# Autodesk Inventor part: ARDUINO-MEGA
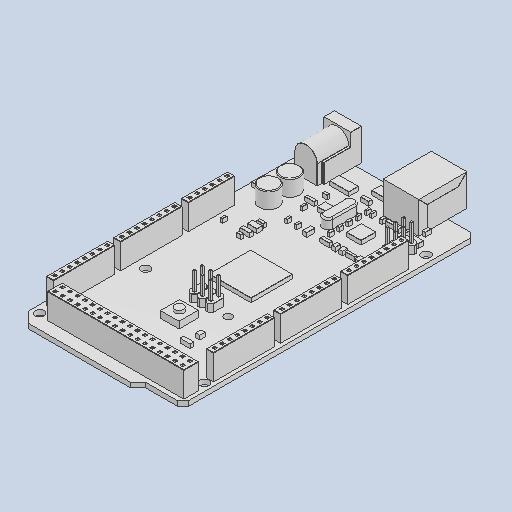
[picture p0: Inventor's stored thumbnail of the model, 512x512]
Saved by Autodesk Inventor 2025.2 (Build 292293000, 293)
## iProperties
Created: 2025-04
Part Number: ARDUINO-MEGA
Material: Generic
Description: PART--DESC
Document SubType Name: Modeling
Designer: BennF
Density: 1 g/cm^3
Appearance: Default
Author: BennF
Revision Number: NONE
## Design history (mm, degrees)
feature "Arduino-Mega"
body "Solid1"
